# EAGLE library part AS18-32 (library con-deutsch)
DEUTSCH Connector
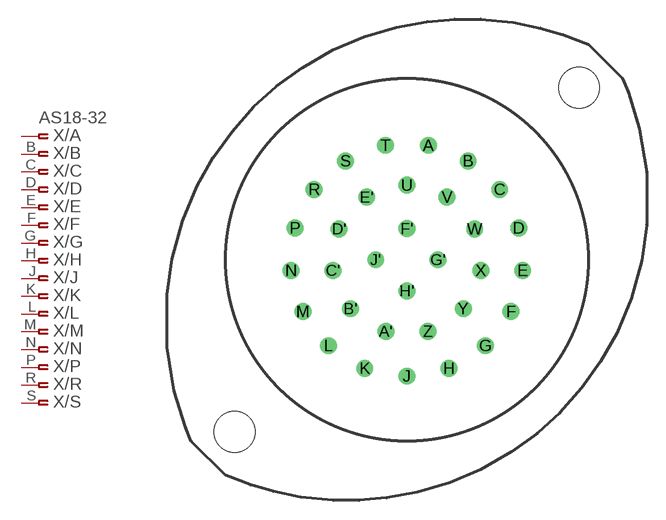
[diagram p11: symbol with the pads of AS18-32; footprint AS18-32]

Designator prefix X; gates /A=PINF_VAL /B=ASPINF /C=ASPINF /D=ASPINF /E=ASPINF /F=ASPINF /G=ASPINF /H=ASPINF /J=ASPINF /K=ASPINF /L=ASPINF /M=ASPINF /N=ASPINF /P=ASPINF /R=ASPINF /S=ASPINF /T=ASPINF /U=ASPINF /V=ASPINF /W=ASPINF /X=ASPINF /Y=ASPINF /Z=ASPINF /A'=PINF_VAL /B'=ASPINF /C'=ASPINF /D'=ASPINF /E'=ASPINF /F'=ASPINF /G'=ASPINF /H'=ASPINF /J'=ASPINF

## AS18-32 (OC_FARNELL: unknown; OC_NEWARK: unknown)  [AS18-32]
A  /A:1  pas
A'  /A':1  pas
B  /B:1  pas
B'  /B':1  pas
C  /C:1  pas
C'  /C':1  pas
D  /D:1  pas
D'  /D':1  pas
E  /E:1  pas
E'  /E':1  pas
F  /F:1  pas
F'  /F':1  pas
G  /G:1  pas
G'  /G':1  pas
H  /H:1  pas
H'  /H':1  pas
J  /J:1  pas
J'  /J':1  pas
K  /K:1  pas
L  /L:1  pas
M  /M:1  pas
N  /N:1  pas
P  /P:1  pas
R  /R:1  pas
S  /S:1  pas
T  /T:1  pas
U  /U:1  pas
V  /V:1  pas
W  /W:1  pas
X  /X:1  pas
Y  /Y:1  pas
Z  /Z:1  pas

## Footprint AS18-32 (pad centres in mm)
DEUTSCH Connector
drill 0.813 round: A 1.676,8.966; A' -1.651,-5.613; B 4.801,7.747; B' -4.42,-3.835; C 7.264,5.512; C' -5.791,-0.838; D 8.763,2.489; D' -5.309,2.413; E 9.068,-0.838; E' -3.15,4.902; F 8.153,-4.064; F' 0,2.438; G 6.147,-6.731; G' 2.438,0; H 3.302,-8.509; H' 0,-2.438; J 0,-9.119; J' -2.438,0; K -3.302,-8.509; L -6.147,-6.731; M -8.153,-4.064; N -9.068,-0.838; P -8.763,2.489; R -7.264,5.512; S -4.801,7.747; T -1.676,8.966; U 0,5.842; V 3.15,4.902; W 5.309,2.413; X 5.791,-0.838; Y 4.42,-3.835; Z 1.651,-5.613
hole 3.2 at -13.49,-13.49
hole 3.2 at 13.49,13.49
